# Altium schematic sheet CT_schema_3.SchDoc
size 396 x 205 mm
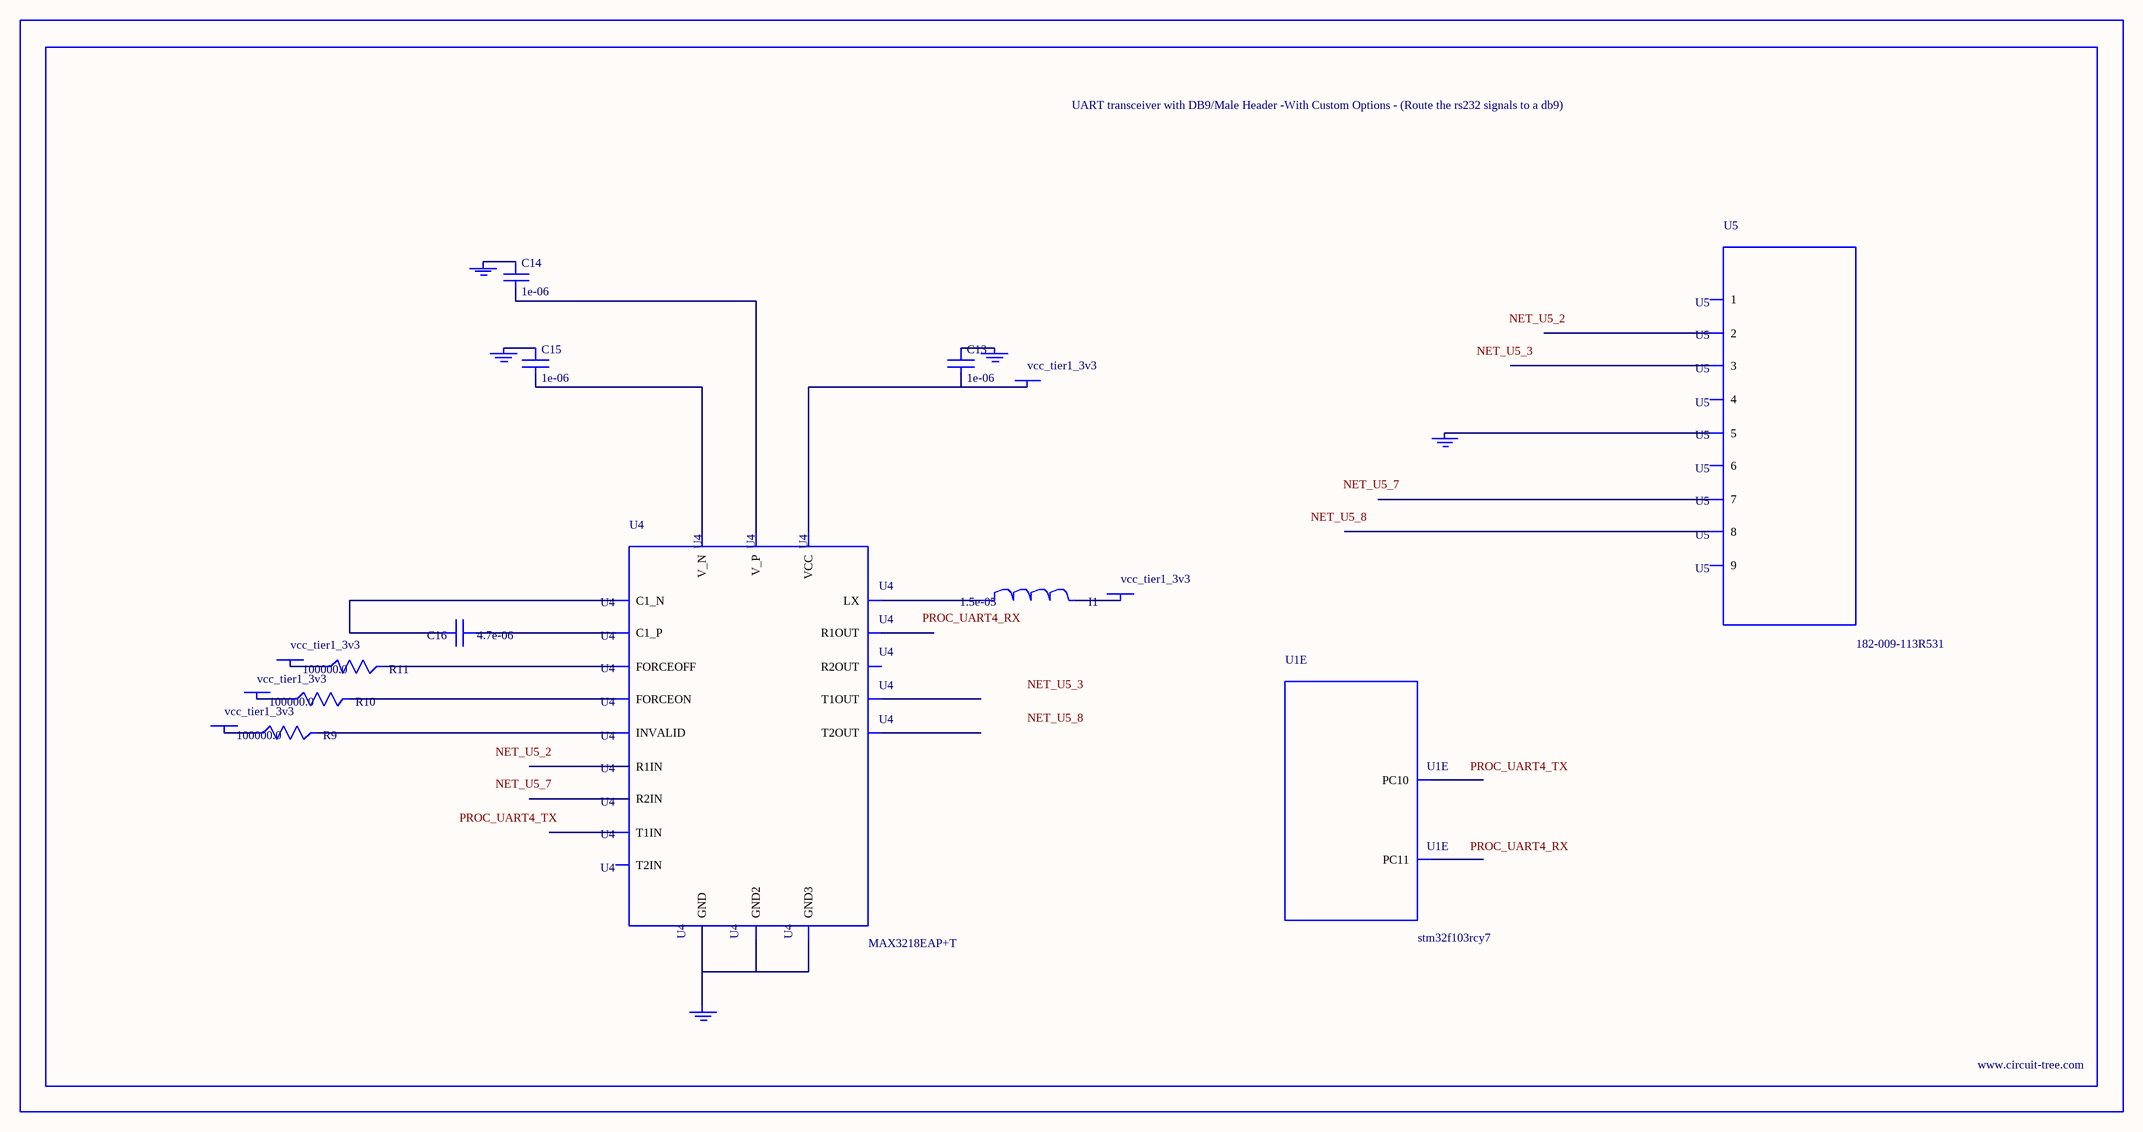
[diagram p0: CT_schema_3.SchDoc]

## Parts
BORDER2  (no value)
C13  1e-06  [C0603]
C14  1e-06  [C0603]
C15  1e-06  [C0603]
C16  4.7e-06  [C0805]
GND_INSTANCE_2_0  (no value)
GND_INSTANCE_2_1  (no value)
GND_INSTANCE_2_2  (no value)
GND_INSTANCE_2_3  (no value)
GND_INSTANCE_2_4  (no value)
I1  1.5e-05  [L1210]
POWER_INSTANCE_2_0  vcc_tier1_3v3
POWER_INSTANCE_2_1  vcc_tier1_3v3
POWER_INSTANCE_2_2  vcc_tier1_3v3
POWER_INSTANCE_2_3  vcc_tier1_3v3
POWER_INSTANCE_2_4  vcc_tier1_3v3
R9  100000.0  [R0603]
R10  100000.0  [R0603]
R11  100000.0  [R0603]
U1  stm32f103rcy7  [WLCSP64]  (part E of 7)
U4  MAX3218EAP+T  [SSOP-20]
U5  182-009-113R531  [182-009-MALE]

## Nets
NetC13_1: C13.1 GND_INSTANCE_2_0.0(GND)
NetC13_2: C13.2 POWER_INSTANCE_2_4.0(PWR) U4.6(VCC)
NetC14_1: C14.1 GND_INSTANCE_2_2.0(GND)
NetC14_2: C14.2 U4.19(V_P)
NetC15_1: C15.1 GND_INSTANCE_2_1.0(GND)
NetC15_2: C15.2 U4.15(V_N)
NetC16_1: C16.1 U4.18(C1_P)
NetC16_2: C16.2 U4.16(C1_N)
NetGND_INSTANCE_2_3_0: GND_INSTANCE_2_3.0(GND) U4.5(GND) U4.17(GND2) U4.20(GND3)
NetGND_INSTANCE_2_4_0: GND_INSTANCE_2_4.0(GND) U5.5
NetI1_1: I1.1 U4.1(LX)
NetI1_2: I1.2 POWER_INSTANCE_2_0.0(PWR)
NetPOWER_INSTANCE_2_1_0: POWER_INSTANCE_2_1.0(PWR) R9.1
NetPOWER_INSTANCE_2_2_0: POWER_INSTANCE_2_2.0(PWR) R10.1
NetPOWER_INSTANCE_2_3_0: POWER_INSTANCE_2_3.0(PWR) R11.1
NetR9_2: R9.2 U4.2(INVALID)
NetR10_2: R10.2 U4.3(FORCEON)
NetR11_2: R11.2 U4.4(FORCEOFF)

Not connected (* = marked no-connect by the designer): U1 A2(PC10) B3(PC11); U4 7(T1IN) 8(T2IN) 9(R1OUT) 10(R2OUT) 11(R2IN) 12(R1IN) 13(T2OUT) 14(T1OUT); U5 1 2 3 4 6 7 8 9

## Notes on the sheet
- Labels drawn without touching a wire or pin: NET_U5_2, NET_U5_3, NET_U5_7, NET_U5_8, PROC_UART4_RX, PROC_UART4_TX

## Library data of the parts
BORDER2 = BORDER_PAGE2
C13-C15 = C0603C105K3RACTU
C16 = C0805C475K4RACTU
GND_INSTANCE_2_0-GND_INSTANCE_2_4 = GND
I1 = L1210R150MDWIT
POWER_INSTANCE_2_0-POWER_INSTANCE_2_4 = PWR
R9-R11 = RC0603JR-07100KL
